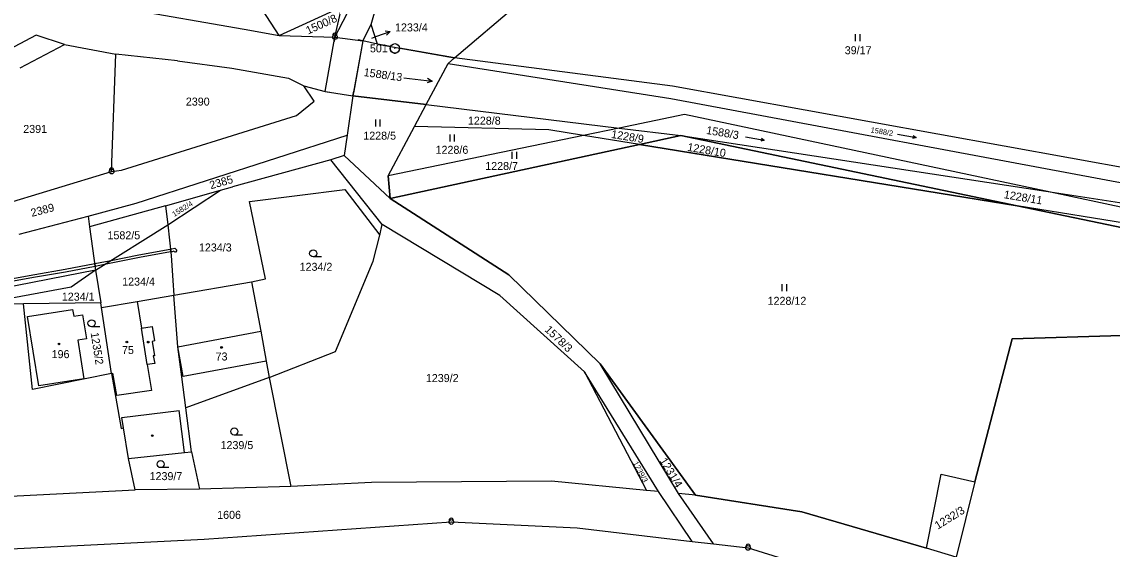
# Model space of a CAD drawing. Extents: x -801826 to -800592, y -1032871 to -1031813.
# Drawn here: x -801689.7 to -801458.2, y -1032516 to -1032403.9 of the extents above; entities that cross this region are included whole.
import ezdxf

# ---------------------------------------------------------------- set-up
doc = ezdxf.new("R2010")
doc.units = 0
for name, color, linetype in [('Vrstva 1', 7, 'Continuous'), ('Vrstva 16', 7, 'Continuous'), ('Vrstva 17', 7, 'Continuous'), ('Vrstva 18', 7, 'Continuous'), ('Vrstva 19', 7, 'Continuous'), ('Vrstva 24', 7, 'Continuous'), ('Vrstva 25', 7, 'Continuous'), ('Vrstva 26', 7, 'Continuous'), ('Vrstva 27', 7, 'Continuous'), ('Vrstva 4', 7, 'Continuous')]:
    doc.layers.add(name, color=color, linetype=linetype)

msp = doc.modelspace()

# ---------------------------------------------------------------- linework, layer by layer
at = {"layer": 'Vrstva 1'}
for p, q in [((-801623.22, -1032407.17), (-801613.02, -1032387.52)), ((-801635.05, -1032406.83), (-801640.52, -1032398.37)), ((-801635.05, -1032406.83), (-801621.73, -1032400.79)), ((-801623.22, -1032407.17), (-801621.73, -1032400.79)), ((-801615.51, -1032404.51), (-801614.36, -1032400.55)), ((-801597.79, -1032411.61), (-801584.32, -1032400.15)), ((-801667.77, -1032401.12), (-801642.46, -1032405.53)), ((-801617.29, -1032407.95), (-801615.51, -1032404.51)), ((-801614.2, -1032408.69), (-801615.51, -1032404.51)), ((-801686.67, -1032406.79), (-801737.87, -1032433.62)), ((-801680.62, -1032408.73), (-801686.67, -1032406.79)), ((-801642.46, -1032405.53), (-801635.05, -1032406.83)), ((-801635.05, -1032406.83), (-801623.22, -1032407.17)), ((-801623.22, -1032407.17), (-801617.29, -1032407.95)), ((-801690.04, -1032413.74), (-801680.62, -1032408.73)), ((-801680.62, -1032408.73), (-801669.71, -1032410.8)), ((-801617.29, -1032407.95), (-801619.39, -1032419.63)), ((-801614.2, -1032408.69), (-801617.29, -1032407.95)), ((-801614.2, -1032408.69), (-801617.29, -1032407.95)), ((-801614.2, -1032408.69), (-801597.79, -1032411.61)), ((-801611.41, -1032409.19), (-801614.2, -1032408.69)), ((-801597.79, -1032411.61), (-801609.49, -1032409.53)), ((-801670.63, -1032435.77), (-801669.71, -1032410.8)), ((-801656.61, -1032412.23), (-801669.71, -1032410.8)), ((-801656.61, -1032412.23), (-801645.12, -1032413.77)), ((-801599.17, -1032412.78), (-801597.79, -1032411.61)), ((-801599.17, -1032412.78), (-801597.79, -1032411.61)), ((-801551.54, -1032417.61), (-801597.79, -1032411.61)), ((-801645.12, -1032413.77), (-801633.07, -1032415.89)), ((-801603.84, -1032421.52), (-801599.17, -1032412.78)), ((-801603.84, -1032421.52), (-801599.17, -1032412.78)), ((-801599.17, -1032412.78), (-801551.9, -1032420.25)), ((-801633.07, -1032415.89), (-801629.81, -1032417.51)), ((-801627.6, -1032420.82), (-801629.81, -1032417.51)), ((-801629.81, -1032417.51), (-801625.27, -1032418.74)), ((-801625.27, -1032418.74), (-801619.39, -1032419.63)), ((-801451.09, -1032435.8), (-801551.54, -1032417.61)), ((-801631.37, -1032423.84), (-801627.6, -1032420.82)), ((-801619.39, -1032419.63), (-801620.64, -1032428.04)), ((-801619.39, -1032419.63), (-801620.64, -1032428.04)), ((-801619.39, -1032419.63), (-801603.84, -1032421.52)), ((-801603.84, -1032421.52), (-801619.39, -1032419.63)), ((-801619.39, -1032419.63), (-801603.84, -1032421.52)), ((-801606.32, -1032426.15), (-801603.84, -1032421.52)), ((-801606.32, -1032426.15), (-801603.84, -1032421.52)), ((-801603.84, -1032421.52), (-801562.83, -1032426.5)), ((-801551.9, -1032420.25), (-801454.13, -1032438.52)), ((-801668.52, -1032435.48), (-801631.37, -1032423.84)), ((-801548.95, -1032423.63), (-801562.83, -1032426.5)), ((-801472.22, -1032439.95), (-801548.95, -1032423.63)), ((-801611.91, -1032436.66), (-801606.32, -1032426.15)), ((-801611.91, -1032436.66), (-801606.32, -1032426.15)), ((-801577.79, -1032426.89), (-801606.32, -1032426.15)), ((-801665.43, -1032442.5), (-801620.64, -1032428.04)), ((-801620.64, -1032428.04), (-801621.28, -1032432.37)), ((-801620.64, -1032428.04), (-801621.28, -1032432.37)), ((-801570.45, -1032428.08), (-801611.91, -1032436.66)), ((-801570.45, -1032428.08), (-801577.79, -1032426.89)), ((-801562.83, -1032426.5), (-801570.45, -1032428.08)), ((-801558.56, -1032430.01), (-801570.45, -1032428.08)), ((-801562.83, -1032426.5), (-801549.75, -1032428.09)), ((-801558.56, -1032430.01), (-801549.75, -1032428.09)), ((-801549.75, -1032428.09), (-801558.56, -1032430.01)), ((-801549.75, -1032428.09), (-801478.34, -1032443.01)), ((-801549.75, -1032428.09), (-801472.22, -1032439.95)), ((-801478.34, -1032443.01), (-801549.75, -1032428.09)), ((-801611.46, -1032441.51), (-801558.56, -1032430.01)), ((-801558.56, -1032430.01), (-801611.46, -1032441.51)), ((-801478.34, -1032443.01), (-801558.56, -1032430.01)), ((-801558.56, -1032430.01), (-801478.34, -1032443.01)), ((-801478.34, -1032443.01), (-801558.56, -1032430.01)), ((-801621.28, -1032432.37), (-801624.09, -1032433.25)), ((-801611.46, -1032441.51), (-801621.28, -1032432.37)), ((-801621.28, -1032432.37), (-801611.46, -1032441.51)), ((-801670.63, -1032435.77), (-801668.52, -1032435.48)), ((-801624.09, -1032433.25), (-801644.93, -1032438.97)), ((-801613.15, -1032446.97), (-801624.09, -1032433.25)), ((-801695.4, -1032443.28), (-801670.63, -1032435.77)), ((-801611.91, -1032436.66), (-801611.46, -1032441.51)), ((-801611.46, -1032441.51), (-801611.91, -1032436.66)), ((-801659.16, -1032443.01), (-801647.53, -1032439.71)), ((-801658.71, -1032447.09), (-801647.53, -1032439.71)), ((-801647.53, -1032439.71), (-801644.93, -1032438.97)), ((-801641.34, -1032442.09), (-801621.08, -1032439.59)), ((-801621.08, -1032439.59), (-801613.7, -1032449.28)), ((-801454.37, -1032443.75), (-801472.22, -1032439.95)), ((-801472.22, -1032439.95), (-801418.97, -1032448.1)), ((-801637.98, -1032458.53), (-801641.34, -1032442.09)), ((-801586.25, -1032457.69), (-801611.46, -1032441.51)), ((-801611.46, -1032441.51), (-801586.25, -1032457.69)), ((-801675.62, -1032445.2), (-801665.43, -1032442.5)), ((-801659.16, -1032443.01), (-801675.3, -1032447.5)), ((-801659.16, -1032443.01), (-801658.71, -1032447.09)), ((-801421.82, -1032452.17), (-801478.34, -1032443.01)), ((-801478.34, -1032443.01), (-801454.22, -1032448.05)), ((-801454.22, -1032448.05), (-801478.34, -1032443.01)), ((-801690.26, -1032449.08), (-801675.62, -1032445.2)), ((-801675.62, -1032445.2), (-801675.3, -1032447.5)), ((-801674.04, -1032456.69), (-801658.71, -1032447.09)), ((-801658.71, -1032447.09), (-801657.98, -1032453.6)), ((-801613.7, -1032449.28), (-801613.15, -1032446.97)), ((-801588.21, -1032462.12), (-801613.15, -1032446.97)), ((-801675.3, -1032447.5), (-801674.04, -1032456.69)), ((-801615.1, -1032454.79), (-801613.7, -1032449.28)), ((-801657.98, -1032453.6), (-801657.65, -1032458.87)), ((-801623.07, -1032473.98), (-801615.1, -1032454.79)), ((-801674.04, -1032456.69), (-801693.97, -1032460.57)), ((-801674.04, -1032456.69), (-801679.19, -1032460.32)), ((-801674.04, -1032456.69), (-801672.95, -1032463.68)), ((-801640.9, -1032459.15), (-801637.98, -1032458.53)), ((-801566.92, -1032476.61), (-801586.25, -1032457.69)), ((-801586.25, -1032457.69), (-801566.92, -1032476.61)), ((-801679.19, -1032460.32), (-801698.85, -1032463.99)), ((-801657.65, -1032458.87), (-801657.45, -1032462.05)), ((-801657.45, -1032462.05), (-801640.9, -1032459.15)), ((-801640.9, -1032459.15), (-801638.95, -1032469.67)), ((-801665.23, -1032463.39), (-801657.45, -1032462.05)), ((-801656.6, -1032473.01), (-801657.45, -1032462.05)), ((-801570.2, -1032478.31), (-801588.21, -1032462.12)), ((-801689.37, -1032463.87), (-801698.85, -1032463.99)), ((-801672.95, -1032463.68), (-801689.37, -1032463.87)), ((-801687.41, -1032482.05), (-801689.37, -1032463.87)), ((-801688.48, -1032466.56), (-801678.93, -1032465.06)), ((-801678.93, -1032465.06), (-801678.68, -1032466.48)), ((-801672.8, -1032464.65), (-801672.95, -1032463.68)), ((-801672.8, -1032464.65), (-801665.23, -1032463.39)), ((-801670.65, -1032478.66), (-801672.8, -1032464.65)), ((-801686.1, -1032481.29), (-801688.48, -1032466.56)), ((-801678.68, -1032466.48), (-801676.82, -1032466.2)), ((-801676.82, -1032466.2), (-801676, -1032471.31)), ((-801638.95, -1032469.67), (-801637.8, -1032476.06)), ((-801676, -1032471.31), (-801677.83, -1032471.6)), ((-801677.83, -1032471.6), (-801676.52, -1032479.77)), ((-801487.3, -1032501.66), (-801479.37, -1032471.31)), ((-801487.3, -1032501.66), (-801479.37, -1032471.31)), ((-801479.37, -1032471.31), (-801487.3, -1032501.66)), ((-801479.37, -1032471.31), (-801456.14, -1032470.6)), ((-801479.37, -1032471.31), (-801456.14, -1032470.6)), ((-801456.14, -1032470.6), (-801479.37, -1032471.31)), ((-801655.7, -1032479.35), (-801656.6, -1032473.01)), ((-801637.17, -1032479.5), (-801623.07, -1032473.98)), ((-801637.8, -1032476.06), (-801637.17, -1032479.5)), ((-801546.62, -1032504.5), (-801566.92, -1032476.61)), ((-801550.24, -1032504.15), (-801566.92, -1032476.61)), ((-801566.92, -1032476.61), (-801546.62, -1032504.5)), ((-801670.65, -1032478.66), (-801687.41, -1032482.05)), ((-801670.65, -1032478.66), (-801668.63, -1032490.38)), ((-801654.85, -1032485.98), (-801655.7, -1032479.35)), ((-801637.17, -1032479.5), (-801654.85, -1032485.98)), ((-801637.17, -1032479.5), (-801632.58, -1032502.64)), ((-801554.5, -1032503.74), (-801570.2, -1032478.31)), ((-801570.2, -1032478.31), (-801557.04, -1032503.49)), ((-801676.52, -1032479.77), (-801686.1, -1032481.29)), ((-801653.65, -1032495.29), (-801654.85, -1032485.98)), ((-801668.63, -1032490.38), (-801668.1, -1032490.19)), ((-801667.08, -1032496.72), (-801668.1, -1032490.19)), ((-801667.08, -1032496.72), (-801655.19, -1032495.45)), ((-801655.19, -1032495.45), (-801653.65, -1032495.29)), ((-801653.65, -1032495.29), (-801652, -1032503.2)), ((-801665.64, -1032503.36), (-801667.08, -1032496.72)), ((-801497.58, -1032515.78), (-801494.5, -1032500.03)), ((-801497.58, -1032515.78), (-801494.5, -1032500.03)), ((-801494.5, -1032500.03), (-801487.3, -1032501.66)), ((-801494.5, -1032500.03), (-801487.3, -1032501.66)), ((-801632.58, -1032502.64), (-801652, -1032503.2)), ((-801615.42, -1032501.8), (-801632.58, -1032502.64)), ((-801577.19, -1032501.54), (-801615.42, -1032501.8)), ((-801557.04, -1032503.49), (-801577.19, -1032501.54)), ((-801487.3, -1032501.66), (-801491.28, -1032517.71)), ((-801487.3, -1032501.66), (-801491.28, -1032517.71)), ((-801714.97, -1032505.84), (-801665.64, -1032503.36)), ((-801652, -1032503.2), (-801665.64, -1032503.36)), ((-801554.5, -1032503.74), (-801557.04, -1032503.49)), ((-801547.32, -1032514.33), (-801554.5, -1032503.74)), ((-801546.62, -1032504.5), (-801550.24, -1032504.15)), ((-801542.85, -1032514.85), (-801550.24, -1032504.15)), ((-801524.04, -1032508.05), (-801546.62, -1032504.5)), ((-801546.62, -1032504.5), (-801524.04, -1032508.05)), ((-801497.58, -1032515.78), (-801524.04, -1032508.05)), ((-801524.04, -1032508.05), (-801497.58, -1032515.78)), ((-801650.95, -1032513.86), (-801598.5, -1032510.21)), ((-801598.5, -1032510.21), (-801571.75, -1032511.45)), ((-801571.75, -1032511.45), (-801547.32, -1032514.33)), ((-801697.53, -1032516.2), (-801650.95, -1032513.86)), ((-801547.32, -1032514.33), (-801542.85, -1032514.85)), ((-801542.85, -1032514.85), (-801535.48, -1032515.72)), ((-801535.48, -1032515.72), (-801499.48, -1032526.77)), ((-801491.28, -1032517.71), (-801497.58, -1032515.78))]:
    msp.add_line(p, q, dxfattribs=at)
msp.add_lwpolyline([(-801617.29, -1032407.95), (-801619.21, -1032418.65), (-801619.39, -1032419.63)], dxfattribs=at)
msp.add_arc((-801610.49, -1032409.58), 1, 156.8976, 2.9231, dxfattribs=at)
at = {"layer": 'Vrstva 16'}
for p, q in [((-801615.4, -1032407.38), (-801614.28, -1032406.98)), ((-801614.28, -1032406.98), (-801611.45, -1032405.98))]:
    msp.add_line(p, q, dxfattribs=at)
msp.add_lwpolyline([(-801612.56, -1032405.84), (-801611.45, -1032405.98), (-801612.23, -1032406.78)], dxfattribs=at)
at = {"layer": 'Vrstva 24'}
for centre, radius in [((-801623.22, -1032407.17), 0.5), ((-801623.22, -1032407.17), 0.0364), ((-801610.49, -1032409.58), 1), ((-801610.49, -1032409.58), 0.0439), ((-801670.63, -1032435.77), 0.5), ((-801670.63, -1032435.77), 0.0364), ((-801598.5, -1032510.21), 0.5), ((-801598.5, -1032510.21), 0.0364), ((-801535.48, -1032515.72), 0.5), ((-801535.48, -1032515.72), 0.0364)]:
    msp.add_circle(centre, radius, dxfattribs=at)
for centre in [(-801623.22, -1032406.8), (-801670.63, -1032435.4), (-801598.5, -1032509.84), (-801535.48, -1032515.35)]:
    msp.add_arc(centre, 0.45, 344.4473, 196.3778, dxfattribs=at)
at = {"layer": 'Vrstva 25'}
for p, q in [((-801512.71, -1032406.57), (-801512.71, -1032408.07)), ((-801511.69, -1032408.07), (-801511.69, -1032406.57)), ((-801608.55, -1032415.85), (-801602.59, -1032416.53)), ((-801614.61, -1032424.67), (-801614.61, -1032426.17)), ((-801613.58, -1032426.17), (-801613.58, -1032424.67)), ((-801598.82, -1032427.86), (-801598.82, -1032429.36)), ((-801597.8, -1032429.36), (-801597.8, -1032427.86)), ((-801536.02, -1032428.39), (-801532.06, -1032429.09)), ((-801503.77, -1032427.83), (-801499.81, -1032428.53)), ((-801585.64, -1032431.57), (-801585.64, -1032433.07)), ((-801584.61, -1032433.07), (-801584.61, -1032431.57)), ((-801626.08, -1032453.89), (-801627.83, -1032453.89)), ((-801528.3, -1032459.69), (-801528.3, -1032461.19)), ((-801527.28, -1032461.19), (-801527.28, -1032459.69)), ((-801673.15, -1032468.74), (-801674.9, -1032468.74)), ((-801642.83, -1032491.73), (-801644.58, -1032491.73)), ((-801658.46, -1032498.66), (-801660.21, -1032498.66))]:
    msp.add_line(p, q, dxfattribs=at)
for points in [[(-801603.53, -1032415.92), (-801602.59, -1032416.53), (-801603.64, -1032416.91)], [(-801500.41, -1032428.09), (-801499.81, -1032428.53), (-801500.53, -1032428.74)], [(-801532.66, -1032428.65), (-801532.06, -1032429.09), (-801532.78, -1032429.3)]]:
    msp.add_lwpolyline(points, dxfattribs=at)
for centre, radius in [((-801627.83, -1032453.14), 0.75), ((-801674.9, -1032467.99), 0.75), ((-801681.81, -1032472.38), 0.175), ((-801667.39, -1032471.97), 0.175), ((-801662.86, -1032471.99), 0.175), ((-801647.29, -1032473.13), 0.175), ((-801644.58, -1032490.98), 0.75), ((-801662, -1032491.85), 0.175), ((-801660.21, -1032497.91), 0.75)]:
    msp.add_circle(centre, radius, dxfattribs=at)
at = {"layer": 'Vrstva 26'}
for p, q in [((-801623.22, -1032407.17), (-801623.39, -1032408.15)), ((-801617.29, -1032407.95), (-801618.27, -1032407.77)), ((-801625.27, -1032418.74), (-801624.29, -1032418.91)), ((-801619.39, -1032419.63), (-801619.21, -1032418.65))]:
    msp.add_line(p, q, dxfattribs=at)
at = {"layer": 'Vrstva 27'}
for points in [[(-801670.73, -1032454.62), (-801664.82, -1032453.42), (-801658.21, -1032452.21), (-801658.14, -1032452.2), (-801658.07, -1032452.81), (-801658.13, -1032452.81), (-801664.7, -1032454), (-801671.8, -1032455.44), (-801672.15, -1032455.51)], [(-801658.14, -1032452.2), (-801657.86, -1032452.18), (-801657.24, -1032452.04), (-801656.8, -1032452.45), (-801656.91, -1032452.56), (-801656.8, -1032452.66), (-801657, -1032452.88), (-801657.11, -1032452.78), (-801657.22, -1032452.89), (-801657.42, -1032452.7), (-801657.76, -1032452.78), (-801658.07, -1032452.81), (-801658.14, -1032452.2)], [(-801674.23, -1032455.3), (-801674.15, -1032455.9), (-801680.4, -1032457.11), (-801686.82, -1032458.22), (-801691.87, -1032459.13), (-801692.68, -1032459.41), (-801692.73, -1032459.24), (-801692.87, -1032459.28), (-801692.95, -1032458.98), (-801692.82, -1032458.95), (-801692.86, -1032458.83), (-801692.03, -1032458.55), (-801686.92, -1032457.62), (-801680.5, -1032456.51), (-801674.23, -1032455.3)], [(-801672.15, -1032455.51), (-801674.15, -1032455.9), (-801674.23, -1032455.3), (-801671.92, -1032454.86), (-801670.73, -1032454.62)]]:
    msp.add_lwpolyline(points, dxfattribs=at)
at = {"layer": 'Vrstva 4'}
for p, q in [((-801625.27, -1032418.74), (-801623.22, -1032407.17)), ((-801665.23, -1032463.39), (-801664.32, -1032469.02)), ((-801664.32, -1032469.02), (-801662, -1032468.64)), ((-801663.07, -1032476.77), (-801664.32, -1032469.02)), ((-801662, -1032468.64), (-801661.5, -1032471.75)), ((-801656.6, -1032473.01), (-801638.95, -1032469.67)), ((-801661.5, -1032471.75), (-801662, -1032471.83)), ((-801662, -1032471.83), (-801661.5, -1032474.89)), ((-801661.5, -1032474.89), (-801661.8, -1032474.94)), ((-801655.45, -1032479.3), (-801656.6, -1032473.01)), ((-801661.45, -1032476.51), (-801663.07, -1032476.77)), ((-801663.07, -1032476.77), (-801662.19, -1032482.26)), ((-801661.8, -1032474.94), (-801661.45, -1032476.51)), ((-801637.8, -1032476.06), (-801655.45, -1032479.3)), ((-801670.65, -1032478.66), (-801670.36, -1032478.6)), ((-801669.54, -1032483.35), (-801670.36, -1032478.6)), ((-801662.19, -1032482.26), (-801669.54, -1032483.35)), ((-801668.44, -1032488.01), (-801656.28, -1032486.53)), ((-801668.1, -1032490.19), (-801668.44, -1032488.01)), ((-801655.19, -1032495.45), (-801656.28, -1032486.53))]:
    msp.add_line(p, q, dxfattribs=at)

# ---------------------------------------------------------------- texts
at = {"layer": 'Vrstva 16'}
msp.add_text('1233/4', height=1.7, dxfattribs=at).set_placement((-801610.45, -1032405.98))
at = {"layer": 'Vrstva 17'}
msp.add_text('501', height=1.7, dxfattribs=at).set_placement((-801615.78, -1032410.43))
at = {"layer": 'Vrstva 18'}
for s, height, rotation, p in [('1500/8', 1.7, 24.3086, (-801628.91, -1032406.65)), ('1588/13', 1.7, 352.047, (-801617.18, -1032415.45)), ('1588/3', 1.7, 350.6078, (-801544.45, -1032427.75)), ('1228/9', 1.7, 350.7067, (-801564.63, -1032428.59)), ('1588/2', 1.14, 350.5377, (-801509.52, -1032427.43)), ('1228/10', 1.7, 350.411, (-801548.46, -1032431.33)), ('2385', 1.7, 16.1574, (-801649.56, -1032439.53)), ('1228/11', 1.7, 350.5604, (-801481.25, -1032441.4)), ('1582/4', 1.14, 32.0898, (-801657.34, -1032445.42)), ('2389', 1.7, 14.6677, (-801687.56, -1032445.39)), ('1235/2', 1.7, 279.0546, (-801675.1, -1032470.04)), ('1578/3', 1.7, 316.5956, (-801578.8, -1032469.52)), ('1239/3', 1.14, 298.3365, (-801559.97, -1032497.7)), ('1231/4', 1.7, 301.4368, (-801554.35, -1032497.19)), ('1232/3', 1.7, 31.8511, (-801495.18, -1032511.85))]:
    msp.add_text(s, height=height, rotation=rotation, dxfattribs=at).set_placement(p)
for s, height, p in [('1233/4', 0.1, (-801615.61, -1032407.38)), ('39/17', 1.7, (-801514.95, -1032410.83)), ('2390', 1.7, (-801654.87, -1032421.74)), ('2391', 1.7, (-801689.4, -1032427.55)), ('1228/8', 1.7, (-801594.97, -1032425.79)), ('1228/5', 1.7, (-801617.19, -1032428.98)), ('1228/6', 1.7, (-801601.84, -1032431.98)), ('1228/7', 1.7, (-801591.29, -1032435.42)), ('1582/5', 1.7, (-801671.51, -1032450.14)), ('1234/3', 1.7, (-801652.09, -1032452.73)), ('1234/2', 1.7, (-801630.71, -1032456.84)), ('1234/4', 1.7, (-801668.39, -1032459.98)), ('1234/1', 1.7, (-801681.21, -1032463.18)), ('1228/12', 1.7, (-801531.33, -1032464.07)), ('1239/2', 1.7, (-801603.9, -1032480.48)), ('1239/5', 1.7, (-801647.5, -1032494.72)), ('1239/7', 1.7, (-801662.57, -1032501.31)), ('1606', 1.7, (-801648.22, -1032509.54))]:
    msp.add_text(s, height=height, dxfattribs=at).set_placement(p)
at = {"layer": 'Vrstva 19'}
for s, p in [('196', (-801683.37, -1032475.4)), ('75', (-801668.43, -1032474.52)), ('73', (-801648.55, -1032475.9))]:
    msp.add_text(s, height=1.7, dxfattribs=at).set_placement(p)

doc.saveas('drawing.dxf')
